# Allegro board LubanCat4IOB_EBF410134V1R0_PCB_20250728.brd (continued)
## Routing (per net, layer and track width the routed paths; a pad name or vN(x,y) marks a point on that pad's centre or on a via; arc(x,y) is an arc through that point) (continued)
PCIE20_0_RXP: length 112
  TOP w0.15: J5.4 49.68,24.47 49.72,24.44 49.72,24.02 49.26,23.57 48.05,23.57 47.88,23.73 v1(47.48,23.73) ; v1(48.23,55.75) 48.44,55.96 48.44,57.28 54.19,63.04 66.91,63.04 72.09,68.22 90.62,68.22 91.37,68.97 91.37,72.91 92.59,74.13 97.62,74.13 99.58,76.09 103.89,76.09 104.7,76.91 106.65,76.91 107.04,77.3 107.04,77.71 106.8,77.94 J25.25
  BOTTOM w0.15: v1(48.23,55.75) 48.44,55.55 48.44,54.31 49.53,53.22 49.53,27.9 arc(49.47,27.75) 49.32,27.69 arc(49.17,27.63) 49.1,27.48 49.1,27.3 arc(49.17,27.15) 49.32,27.09 arc(49.47,27.03) 49.53,26.88 49.53,25.37 arc(49.47,25.23) 49.33,25.17 arc(49.18,25.11) 49.12,24.97 49.12,24.77 arc(49.18,24.63) 49.33,24.57 arc(49.47,24.51) 49.53,24.37 49.53,24.08 49.01,23.57 48.05,23.57 47.88,23.73 v1(47.48,23.73)
PCIE20_0_TXN: length 94.2
  TOP w0.15: v1(48.57,58.78) 48.42,58.93 48.42,59.14 53.36,64.08 66.38,64.08 71.51,69.21 89.21,69.21 89.7,69.71 89.7,70.53 C156.1 ; v1(52.65,23.79) 52.24,23.79 52.08,23.62 51.25,23.62 50.84,24.02 50.84,24.44 50.88,24.47 J5.10
  BOTTOM w0.15: v1(52.65,23.79) 52.24,23.79 52.08,23.62 51.7,23.62 51.44,23.89 51.44,24.72 51.79,25.07 53.22,25.07 53.92,25.78 53.92,29.04 52.76,30.21 52.76,31.95 arc(52.82,32.11) 52.98,32.18 arc(53.15,32.24) 53.21,32.41 53.21,32.55 arc(53.15,32.71) 52.98,32.78 arc(52.82,32.84) 52.76,33.01 52.76,33.15 arc(52.82,33.31) 52.98,33.38 arc(53.15,33.44) 53.21,33.6 53.21,33.75 arc(53.15,33.91) 52.98,33.98 arc(52.82,34.04) 52.76,34.2 52.76,57.23 52.02,57.96 48.72,57.96 48.4,58.27 48.4,58.62 v1(48.57,58.78)
PCIE20_0_TXP: length 94.3
  TOP w0.15: v1(52.65,23.13) 52.24,23.13 52.08,23.29 51.11,23.29 50.52,23.89 50.52,24.44 50.48,24.47 J5.8 ; v1(47.91,58.78) 48.09,58.96 48.09,58.98 48.1,58.99 48.1,59.28 53.23,64.41 66.24,64.41 71.37,69.54 89.07,69.54 89.37,69.84 89.37,70.53 C157.1
  BOTTOM w0.15: v1(52.65,23.13) 52.24,23.13 52.08,23.29 51.56,23.29 51.11,23.75 51.11,24.86 51.65,25.4 53.08,25.4 53.6,25.92 53.6,28.9 52.43,30.07 52.43,57.09 51.88,57.63 48.58,57.63 48.08,58.14 48.08,58.62 v1(47.91,58.78)
PCIE20X1_2_CLKREQN_M0: length 66.3
  TOP w0.152: v1(61.65,81.41) 61.15,80.91 61.15,79.45 59.68,77.98 J6.54
  ART03 w0.14: v1(61.65,81.41) 61.65,82.35 62.23,82.93 69.24,82.93 70.54,81.63 76.94,81.63 77.24,81.94 80.31,81.94 80.77,81.48 88.72,81.48 89.28,82.04 96.77,82.04 97.28,81.53 105.85,81.53 106.86,80.52 v1(116.71,80.52)
  BOTTOM w0.152: R179.1 116.71,79.38 v1(116.71,80.52)
PCIE20X1_2_PERSTN_M0: length 60.1
  TOP w0.152: J6.74 63.68,76.73 66.15,79.2 v1(66.15,80.39)
  TOP w0.203: v1(97.28,65.91) 98.17,65.02 99.31,65.02 100.84,66.55 101.85,66.55 103.89,68.58 R181.2
  ART03 w0.14: v1(66.15,80.39) 67.98,78.56 79.48,78.56 79.96,79.04 89.88,79.04 90.56,78.36 95.58,78.36 v1(95.7,78.48)
  BOTTOM w0.203: v1(97.28,65.91) 97.41,66.04 97.41,67.23 98.12,67.94 98.12,75.65 95.7,78.07 v1(95.7,78.48)
PCIE20X1_2_WAKEN_M0: length 68.5
  TOP w0.152: v1(61.65,80.39) 61.65,79.35 60.08,77.77 J6.56
  ART03 w0.14: v1(118.88,80.52) 118.36,80.52 117.3,79.46 97.81,79.46 96.22,81.05 90.32,81.05 89.26,79.98 77.27,79.98 76.73,80.52 69.39,80.52 68.5,81.41 64.26,81.41 63.98,81.13 63.98,79.95 63.7,79.67 61.93,79.67 61.65,79.95 v1(61.65,80.39)
  BOTTOM w0.152: v1(118.88,80.52) R178.1
PE_TXN: length 21
  TOP w0.15: J25.31 104.4,77.99 104.2,77.79 104.2,77.41 103.69,76.89 98.69,76.89 98.05,76.25 90.1,76.25 89.7,75.85 89.7,72.67 90.04,72.33 C156.2
PE_TXP: length 21.1
  TOP w0.15: J25.33 103.6,78.01 103.88,77.73 103.88,77.54 103.55,77.21 98.55,77.21 97.92,76.58 89.96,76.58 89.37,75.99 89.37,72.67 89.03,72.33 C157.2
PHY1_CLKOUT125: length 4.6
  BOTTOM w0.132: R97.2 107.19,66.17 107.19,67.81 107.45,68.08 109.09,68.08 U14.35
PHY1_LED1: length 59
  BOTTOM w0.152: J15.14 107.64,99 106.55,97.92 106.55,84.73 106.02,84.2 98.93,84.2 98.3,83.56 98.3,79.75 100.97,77.09 100.97,63.12 101.68,62.41 103.8,62.41 R103.1 105.04,63.65 106.07,63.65 108.01,65.59 108.01,66.86 108.47,67.32 U14.33
PHY1_LED2: length 69.7
  BOTTOM w0.152: U14.34 107.86,67.73 107.64,67.5 107.64,65.7 106.83,64.9 105.15,64.9 R102.1 103.9,63.65 101.53,63.65 101.35,63.83 101.35,77.34 98.81,79.88 98.81,83.31 99.19,83.69 106.53,83.69 106.98,84.15 106.98,96.54 107.21,96.77 121.4,96.77 J15.11
PWM7_IR_M0: length 62.8
  TOP w0.152: v1(15.37,12.06) 15.77,11.66 18.16,11.66 18.67,12.17 18.67,16.59 18.97,16.89 62.23,16.89 63.5,18.16 63.5,22.99 62.88,23.61 J5.70
  BOTTOM w0.152: R45.1 C46.1 v1(15.37,12.06)
PWRON_EN: length 4.2
  TOP w0.152: v1(27.3,22.48) 27.66,22.48 28.11,22.93 J3.24
  BOTTOM w0.152: R238.2 v1(27.3,22.48)
PWRON_KEY: length 35.2
  TOP w0.152: v1(8.13,21.84) 8.66,21.31 28.42,21.31 28.91,21.8 J3.28
  TOP w0.381: SW1.3 v1(3.43,20.07) SW1.4
  BOTTOM w0.152: v1(3.43,20.07) 3.45,20.06 Z1.2 C39.1 5.21,21.33 5.71,21.84 v1(8.13,21.84)
RESET_KEY: length 33.5
  TOP w0.203: J3.26 28.51,22.57 27.79,21.84 9.14,21.84 v1(8.13,22.86)
  TOP w0.381: SW2.3 v1(3.49,24.46) SW2.4
  BOTTOM w0.254: v1(8.13,22.86) 6.47,24.52 C41.1 Z2.2 3.55,24.52 v1(3.49,24.46)
RS485_1_A: length 31
  TOP w0.305: R67.1 93.34,19.14 93.67,19.46 J11.1
  BOTTOM w0.305: J11.1 92.76,19.76 91.57,19.76 91.26,20.06 91.26,21.65 90.5,22.41 90.5,31.68 D20.2 90.5,35.34 90.5,40.83 R62.2 90.52,41.44 90.52,42.13 90.93,42.54 U10.6
RS485_1_B: length 32.7
  TOP w0.305: R66.1 R63.1 v1(94.83,19.3)
  BOTTOM w0.305: U10.7 89.66,42.54 90.06,42.15 90.06,41.63 89.65,41.23 R64.1 90.04,40.76 90.04,35.29 D18.2 90.04,31.73 90.04,22.22 90.81,21.46 90.81,19.88 91.38,19.3 v1(94.83,19.3)
RS485_2_A: length 30.9
  TOP w0.305: J13.1 85.92,19.46 85.72,19.27 R69.1
  BOTTOM w0.305: J13.1 85.01,19.76 84.2,19.76 83.71,20.25 83.71,29.1 82.58,30.23 82.58,31.63 D22.2 82.62,35.34 82.62,40.83 R70.2 82.63,41.46 82.63,41.99 83.06,42.42 U11.6
RS485_2_B: length 32.6
  TOP w0.305: v1(87.21,19.3) R71.1 R68.1
  BOTTOM w0.305: v1(87.21,19.3) 84.01,19.3 83.25,20.06 83.25,28.91 82.04,30.12 82.04,31.87 80.4,33.51 D21.2 82.17,35.29 82.17,40.76 R72.1 82.14,41.51 82.14,41.94 81.79,42.29 U11.7
RTC_32K_IN: length 132.8
  TOP w0.152: J5.50 58.88,23.45 54.36,18.92 32.13,18.92 31.37,18.16 18.41,18.16 17.91,17.65 17.91,13.33 v1(17.27,12.7)
  ART03 w0.14: v1(3.3,79.88) 3.3,71.82 3.12,71.64 3.12,69.36 2.67,68.9 2.67,59.74 3.07,59.33 3.07,42.77 5.08,40.77 5.08,19.12 9.21,14.98 17.27,14.98 17.78,14.48 17.78,13.21 v1(17.27,12.7)
  BOTTOM w0.152: R48.2 5.46,80.39 4.95,79.88 v1(3.3,79.88)
RTC_INT: length 135.4
  TOP w0.152: v1(17.27,13.71) 17.27,18.03 17.91,18.67 30.99,18.67 31.75,19.43 53.98,19.43 58.48,23.93 J5.48
  ART03 w0.152: v1(17.27,13.71) 9.14,13.71 4.45,18.41 4.45,40.38 2.06,42.77 2.06,69.62 2.49,70.05 2.49,71.07 2.06,71.5 2.06,79.04 2.54,79.53 v1(2.54,82.68)
  BOTTOM w0.152: U8.3 1.59,85.41 1.27,85.09 1.27,83.06 1.65,82.68 v1(2.54,82.68) 2.55,82.67 R46.2
RXD1_232: length 37.6
  BOTTOM w0.254: R51.1 36.45,29.59 35.31,30.73 D8.2 33.03,33.51 32.46,34.09 32.46,40.08 34.67,42.29 34.67,44.96 36.45,46.73 41.53,46.73 41.79,46.99 U9.13
RXD2_232: length 27
  BOTTOM w0.254: U9.8 36.71,39.87 37.21,39.37 37.21,36.7 38,35.91 40.65,35.91 D7.2 42.92,33.38 42.92,23.25 44.07,22.1 R49.1
SARADC_BOOT: length 78.4
  TOP w0.152: J4.52 33.71,77.3 32.38,78.63 32.38,79.01 29.67,81.73 18.62,81.73 v1(18.05,82.29)
  BOTTOM w0.152: R239.2 6.23,40.78 7.37,40.78 7.58,40.57 11.54,40.57 12.52,41.54 12.52,58.23 15.34,61.05 15.34,68.57 14.96,68.95 11.48,68.95 10.69,69.74 10.69,71.31 10.13,71.87 10.13,74.56 12.88,77.31 12.88,79.62 13.26,80 14.4,80 15.16,80.76 15.16,81.68 15.78,82.29 v1(18.05,82.29)
SARADC_IN1/REC: length 80.9
  TOP w0.203: J4.50 33.31,77.15 29.45,81.01 17.55,81.01 v1(17.08,81.48)
  BOTTOM w0.203: R28.2 8.5,27.82 10.41,29.73 10.41,35.57 15.11,40.27 15.11,57.02 17.91,59.82 17.91,68.85 17.27,69.48 17.27,71.01 17.65,71.39 17.65,77.87 18.01,78.22 18.01,80.55 v1(17.08,81.48)
SARADC_IN4: length 70.1
  TOP w0.203: J4.46 32.51,76.22 28.26,80.48 v1(17.08,80.48)
  BOTTOM w0.203: R31.2 8.96,35.31 14.35,40.71 14.35,57.42 16.76,59.83 16.76,71.39 17.05,71.68 17.05,78.49 17.6,79.04 17.6,79.96 v1(17.08,80.48)
SARADC_IN5: length 65.7
  TOP w0.203: v1(17.08,79.48) 17.48,79.87 28.13,79.87 32.11,75.89 J4.44
  BOTTOM w0.203: v1(17.08,79.48) 16.26,78.65 16.26,70.75 15.94,70.44 15.94,60.4 13.34,57.8 13.34,40.99 8.94,36.59 R33.2
SBU_1: length 26.7
  TOP w0.135: v1(27.07,95) 27.12,95.05 J30.A8
  BOTTOM w0.135: v1(27.07,95) 25.87,96.19 25.87,99.66 26.25,100.04 29.75,100.04 30.26,99.53 30.26,99.37 30.76,98.87 35.11,98.87 35.54,98.44 35.54,97.71 35.45,97.62 U37.1 U37.10 35.45,95.67 35.54,95.58 35.54,95.39 35.28,95.12 33.69,95.12 32.36,93.79 32.36,93.45 R229.1
  BOTTOM w0.152: R226.1 C201.1 32,92.07 R229.1
SBU_2: length 19.1
  TOP w0.135: v1(30.73,99.57) 30.23,99.57 29.72,99.06 29.27,99.06 28.96,98.74 28.96,98.04 28.87,97.96 J30.B8
  BOTTOM w0.135: v1(30.73,99.57) 30.73,99.39 30.94,99.19 35.24,99.19 35.86,98.57 35.86,97.71 35.95,97.62 U37.2 U37.9 35.95,95.67 35.86,95.58 35.86,95.26 35.41,94.81 33.82,94.81 32.67,93.66 32.67,93.45 R228.1
  BOTTOM w0.152: R228.1 33.03,92.07 C202.1 R227.1
SDMMC_CLK: length 87.7
  TOP w0.132: J6.77 64.48,70.08 64.95,69.6 v1(65.63,69.6) ; v1(107.14,27.98) 107.36,27.98 R57.1
  BOTTOM w0.132: v1(65.63,69.6) 66.14,69.1 66.14,67.86 66.4,67.6 67.87,67.6 68.16,67.31 68.16,56.5 70.78,53.88 95.57,53.88 101.85,47.59 101.85,41.01 101.99,40.88 102.51,40.88 102.64,40.75 102.64,40.48 102.51,40.35 101.99,40.35 101.85,40.22 101.85,39.95 101.99,39.82 102.51,39.82 102.64,39.69 102.64,39.43 102.51,39.29 101.99,39.29 101.85,39.16 101.85,38.9 101.99,38.76 102.51,38.76 102.64,38.63 102.64,38.37 102.51,38.24 101.99,38.24 101.85,38.1 101.85,37.84 101.99,37.71 102.51,37.71 102.64,37.58 102.64,37.31 102.51,37.18 101.99,37.18 101.85,37.05 101.85,36.78 101.99,36.65 102.51,36.65 102.64,36.52 102.64,36.26 102.51,36.12 101.99,36.12 101.85,35.99 101.85,35.73 101.99,35.59 102.51,35.59 102.64,35.46 102.64,35.2 102.51,35.07 101.99,35.07 101.85,34.93 101.85,29.85 102.63,29.07 106.58,29.07 107.14,28.51 v1(107.14,27.98)
SDMMC_CMD: length 87.8
  TOP w0.132: J6.79 64.88,70.38 65.14,70.12 66.12,70.12 v1(66.63,69.6) ; R55.1 v1(111.25,29.08)
  BOTTOM w0.132: v1(66.63,69.6) 67.21,69.03 69.64,69.03 69.9,68.76 69.9,67.85 69.77,67.72 69.29,67.72 69.15,67.59 69.15,67.32 69.29,67.19 69.77,67.19 69.9,67.06 69.9,66.8 69.77,66.66 69.29,66.66 69.15,66.53 69.15,66.27 69.29,66.13 69.77,66.13 69.9,66 69.9,65.74 69.77,65.61 69.29,65.61 69.15,65.47 69.15,65.21 69.29,65.08 69.77,65.08 69.9,64.95 69.9,64.68 69.77,64.55 69.29,64.55 69.15,64.42 69.15,56.86 71.26,54.75 95.93,54.75 102.87,47.81 102.87,42.53 103.66,41.75 103.66,34.25 102.87,33.47 102.87,31.06 103.89,30.04 107.34,30.04 107.82,29.56 110.78,29.56 v1(111.25,29.08)
SDMMC_D0: length 88.8
  TOP w0.132: R58.1 106.09,27.98 v1(105.87,27.98) ; v1(65.63,67) 63.25,67 62.88,67.37 J6.69
  BOTTOM w0.132: v1(105.87,27.98) 105.31,27.42 100.81,27.42 100.33,27.9 100.33,47.24 95.01,52.57 67.39,52.57 65.94,54.02 65.94,56.52 66.07,56.66 66.49,56.66 66.62,56.79 66.62,57.05 66.49,57.18 66.07,57.18 65.94,57.32 65.94,57.58 66.07,57.71 66.49,57.71 66.62,57.84 66.62,58.11 66.49,58.24 66.07,58.24 65.94,58.37 65.94,58.64 66.07,58.77 66.49,58.77 66.62,58.9 66.62,59.17 66.49,59.3 66.07,59.3 65.94,59.43 65.94,59.69 66.07,59.83 66.49,59.83 66.62,59.96 66.62,60.22 66.49,60.35 66.07,60.35 65.94,60.49 65.94,60.75 66.07,60.88 66.49,60.88 66.62,61.01 66.62,61.28 66.49,61.41 66.07,61.41 65.94,61.54 65.94,65.78 65.63,66.09 v1(65.63,67)
SDMMC_D1: length 88.1
  TOP w0.132: J6.71 63.28,68 63.68,67.6 65.08,67.6 v1(65.63,68.16) ; v1(104.6,27.98) 104.82,27.98 R59.1
  BOTTOM w0.132: v1(104.6,27.98) 102.29,27.98 100.84,29.43 100.84,47.37 95.2,53 68.79,53 68.66,53.14 68.66,54.26 68.52,54.4 68.26,54.4 68.13,54.26 68.13,53.14 68,53 67.74,53 67.46,53.28 67.46,54.05 67.2,54.31 66.63,54.31 66.5,54.44 66.5,54.71 66.65,54.86 67.58,54.86 67.72,55 67.72,55.26 67.58,55.39 66.63,55.39 66.5,55.52 66.5,55.76 66.63,55.9 67.08,55.9 67.21,56.03 67.21,64 67.08,64.13 66.51,64.13 66.38,64.26 66.38,64.53 66.51,64.66 67.08,64.66 67.21,64.79 67.21,65.47 67.06,65.62 66.71,65.62 66.45,65.89 66.45,66.41 66.13,66.73 66.13,67.21 65.63,67.71 v1(65.63,68.16)
SDMMC_D2: length 88.7
  TOP w0.132: R53.1 113.79,28.7 v1(113.41,29.08) ; J6.73 63.68,69.08 64.06,68.7 66.09,68.7 v1(66.63,68.16)
  BOTTOM w0.132: v1(66.63,68.16) 66.67,68.12 68.43,68.12 68.67,67.88 68.67,56.61 70.97,54.31 95.75,54.31 102.36,47.7 102.36,42.05 103.12,41.29 103.12,34.71 102.36,33.95 102.36,30.95 103.73,29.58 107.06,29.58 108.25,28.39 111.67,28.39 111.94,28.65 111.94,29.49 112.2,29.76 113.15,29.76 113.41,29.49 v1(113.41,29.08)
SDMMC_D3: length 88.6
  TOP w0.132: v1(66.63,67) 67.36,67.73 67.36,68.72 66.98,69.1 64.47,69.1 64.08,69.49 J6.75 ; R54.1 v1(112.52,29.08)
  BOTTOM w0.132: v1(112.52,29.08) 112.52,28.13 111.66,27.27 106.98,27.27 106.6,27.65 106.6,28.28 106.25,28.64 102.45,28.64 101.35,29.74 101.35,47.48 95.39,53.44 70.51,53.44 67.65,56.3 67.65,65.99 v1(66.63,67)
SDMMC_DET: length 77.7
  TOP w0.152: v1(68.63,69.6) 67.74,70.5 65.51,70.5 65.28,70.73 J6.81 ; v1(103.38,31.37) 103.38,29.46 103.89,28.95 R60.1 R61.2
  BOTTOM w0.152: v1(68.63,69.6) 70.12,69.6 70.51,69.21 70.51,56.13 71.45,55.2 96.11,55.2 103.38,47.93 103.38,42.95 104.17,42.16 104.17,33.82 103.38,33.03 v1(103.38,31.37)
SIM_CLK0: length 36.4
  TOP w0.152: J25.12 115.2,69.48 114.94,69.21 114.94,60.2 113.73,59 113.73,57.47 116.97,54.23 116.97,37.46 116.75,37.25 v1(116.71,37.25)
  BOTTOM w0.132: v1(116.71,37.25) R171.1
SIM_DATA0: length 40.5
  TOP w0.152: v1(113.49,36.45) 117.09,36.45 117.47,36.83 117.47,54.48 114.87,57.09 114.87,59.37 115.44,59.94 115.44,68.96 116,69.52 J25.10
  BOTTOM w0.132: R173.1 113.61,36.57 v1(113.49,36.45)
SIM_RST0: length 42.1
  TOP w0.152: v1(113.16,34.8) 112.9,35.05 112.9,36.57 113.28,36.96 115.32,36.96 116.46,38.1 116.46,54.1 112.59,57.97 112.59,58.99 114.55,60.96 114.55,69.11 114.4,69.26 J25.14
  BOTTOM w0.132: R170.1 v1(113.16,34.8)
SIM_VDD: length 61.2
  TOP w0.305: J25.8 116.8,69.56 116.01,68.77 116.01,56.83 118.11,54.74 118.11,37.34 v1(117.98,37.21)
  BOTTOM w0.305: J31.1 110.75,23.29 111.05,23.6 113,23.6 114.43,25.02 114.43,29.59 114.77,29.93 U32.1 113.28,30.87 112.39,31.75 112.39,36.57 113.28,37.46 115.14,37.46 115.44,37.16 ; 115.44,37.16 R169.1 ; 115.44,37.16 116.13,37.84 117.35,37.84 v1(117.98,37.21)
SPK_CTRL: length 45.5
  TOP w0.152: J4.24 28.11,77.68 27.3,78.48 16,78.48 15.6,78.89 15.6,82.4 16,82.8 19.56,82.8 19.94,83.18 v1(19.94,84.48)
  ART03 w0.14: v1(35.69,85.14) 34.56,85.14 34,85.7 27.58,85.7 26.92,86.36 26.31,86.36 25.3,85.34 24.64,85.34 23.77,84.48 v1(19.94,84.48)
  BOTTOM w0.152: U34.1 35.06,83.56 R214.1 35.43,84.89 v1(35.69,85.14)
SS_TXN: length 16.1
  BOTTOM w0.135: C97.1 85.19,83.02 85.19,83.47 85.05,83.61 85.05,84.02 84.95,84.12 U17.7 U17.4 84.95,86.06 85.05,86.16 85.05,87.02 83.82,88.25 83.82,89.34 84.65,90.17 84.65,90.49 85.47,91.31 86.4,91.31 86.65,91.06 87.26,91.06 87.47,91.26 88.37,91.26 88.7,90.93 89.15,90.93 89.76,91.54 89.76,91.75 89.62,91.88 J16.8
SS_TXP: length 16.1
  BOTTOM w0.135: C98.1 85.5,83.02 85.5,83.6 85.36,83.74 85.36,84.02 85.45,84.12 U17.6 U17.5 85.45,86.06 85.36,86.16 85.36,87.15 84.13,88.38 84.13,89.21 84.96,90.04 84.96,90.36 85.6,91 86.27,91 86.52,90.75 87.39,90.75 87.6,90.95 88.24,90.95 88.57,90.62 89.28,90.62 90.07,91.41 90.07,91.75 90.21,91.88 J16.9
SSRX_1N: length 14.4
  TOP w0.135: R223.1 31.35,92.72 U35.5 U35.6 31.35,94.63 31.59,94.87 32.88,94.87 33.91,95.9 33.91,98.47 33.39,98.99 30.33,98.99 29.96,98.63 29.96,98.19 29.87,98.09 J30.B10
SSRX_1P: length 14
  TOP w0.135: J30.B11 30.37,98.03 30.28,98.12 30.28,98.5 30.46,98.68 32.17,98.68 arc(32.26,98.64) 32.3,98.55 arc(32.34,98.46) 32.43,98.42 32.71,98.42 arc(32.8,98.46) 32.84,98.55 arc(32.88,98.64) 32.97,98.68 33.26,98.68 33.59,98.34 33.59,98.08 arc(33.55,97.97) 33.44,97.92 arc(33.33,97.88) 33.28,97.77 33.28,97.54 arc(33.33,97.43) 33.44,97.39 arc(33.55,97.34) 33.59,97.23 33.59,96.03 32.75,95.18 31.46,95.18 30.86,94.58 30.86,94.17 U35.7 U35.4 30.85,92.78 31.4,92.22 31.4,91.97 R222.1
SSRX_2N: length 4.7
  TOP w0.135: R225.1 26.75,92.24 26.75,92.76 26.65,92.85 U36.5 U36.6 26.47,94.34 26.47,94.59 26.47,94.6 26.47,95.13 26.47,95.13 26.47,95.2 26.13,95.54 J30.A10
SSRX_2P: length 4.7
  TOP w0.135: J30.A11 25.63,95.6 26.15,95.07 26.15,95 U36.7 U36.4 26.15,92.91 26.43,92.63 26.43,92.08 R224.1
SSTX_1N: length 4.6
  TOP w0.135: C198.1 29.13,92.24 29.13,92.5 29.35,92.72 U35.1 U35.10 29.35,94.5 29.54,94.69 29.54,95.08 29.63,95.17 J30.A3
SSTX_1P: length 4.6
  TOP w0.135: J30.A2 30.13,95.47 29.94,95.29 29.94,95.04 29.85,94.95 29.85,94.16 U35.9 U35.2 29.85,92.77 29.45,92.37 29.45,92.08 C197.1
SSTX_2N: length 16.3
  TOP w0.135: C200.1 24.65,92.59 U36.1 U36.10 24.65,94.47 24.48,94.64 arc(24.44,94.67) 24.39,94.68 22.75,94.68 arc(22.24,94.78) 21.81,95.07 arc(21.63,95.33) 21.57,95.64 21.57,98.34 arc(21.65,98.72) 21.86,99.04 21.86,99.04 arc(22.2,99.26) 22.59,99.34 25.5,99.34 arc(25.78,99.29) 26.03,99.14 arc(26.21,98.9) 26.28,98.61 26.28,98.19 26.37,98.1 J30.B3
SSTX_2P: length 16.2
  TOP w0.135: C199.1 24.7,92 24.7,92.19 25.15,92.65 U36.2 U36.9 25.15,94.5 arc(25.12,94.68) 25.01,94.84 arc(24.84,94.95) 24.64,94.99 22.75,94.99 arc(22.36,95.07) 22.03,95.29 arc(21.92,95.45) 21.88,95.64 21.88,96.13 arc(21.93,96.25) 22.05,96.3 arc(22.17,96.34) 22.21,96.46 22.21,96.67 arc(22.17,96.79) 22.05,96.83 arc(21.93,96.88) 21.88,97 21.88,97.21 arc(21.93,97.32) 22.05,97.37 arc(22.17,97.42) 22.21,97.54 22.21,97.75 arc(22.17,97.86) 22.05,97.91 arc(21.93,97.96) 21.88,98.08 21.88,98.34 arc(21.94,98.6) 22.08,98.81 arc(22.31,98.97) 22.59,99.02 25.5,99.02 arc(25.67,98.99) 25.83,98.9 arc(25.93,98.77) 25.96,98.61 25.96,98.19 25.87,98.1 J30.B2
SYS_LED: length 57.4
  TOP w0.152: J5.65 v1(62.08,26.77)
  ART03 w0.14: v1(62.08,26.77) 62.08,25.3 61.85,25.07 33.32,25.07 32.99,24.74 32.99,21.62 32.2,20.83 v1(12.06,20.83)
  BOTTOM w0.152: v1(12.06,20.83) 11.44,20.2 R38.1
TX_CEC_PORT: length 10.7
  TOP w0.156: J18.13 68.5,94.74 68.68,94.92 68.68,95.6 68.53,95.76 65.57,95.76 v1(64.93,95.12)
  BOTTOM w0.152: Q9.3 63.75,95.49 D33.2 64.38,95.12 v1(64.93,95.12)
TX_D0N_PORT: length 9.2
  TOP w0.107: J18.9 66.5,91.75 66.39,91.65 66.3,91.65 66.19,91.54 66.19,91.32 66.73,90.79 67.63,90.79 68.21,90.21 U23.4 U23.7 68.21,88.63 67.95,88.38 67.95,87.85 v1(68.05,87.76) 67.85,87.56 67.85,87.33 R136.1
  BOTTOM w0.107: R136.1 67.84,87.34 67.84,87.55 v1(68.05,87.76)
TX_D0P_PORT: length 9.2
  TOP w0.107: R134.1 67.57,87.37 67.57,87.57 v1(67.39,87.76) 67.67,88.04 67.67,88.5 67.71,88.53 U23.6 U23.5 67.71,90.31 67.51,90.5 66.61,90.5 65.91,91.2 65.91,91.54 65.8,91.65 65.61,91.65 65.5,91.75 J18.7
  BOTTOM w0.107: R134.1 67.56,87.36 67.56,87.59 v1(67.39,87.76)
TX_D1N_PORT: length 8.1
  TOP w0.107: J18.6 65,91.75 64.89,91.65 64.8,91.65 64.69,91.54 64.69,91.39 65.07,91.01 65.07,90.77 65.26,90.59 U22.1 U22.10 65.26,88.56 65.46,88.37 65.46,88.09 65.71,87.83 65.71,87.81 v1(65.76,87.76) 65.56,87.55 65.56,87.34 R138.1
  BOTTOM w0.107: v1(65.76,87.76) 65.56,87.56 65.56,87.34 R138.1
TX_D1P_PORT: length 8.1
  TOP w0.107: R137.1 65.27,87.36 65.27,87.58 v1(65.1,87.76) 65.17,87.83 65.17,88.25 64.76,88.66 U22.9 U22.2 64.76,90.63 64.79,90.66 64.79,90.89 64.41,91.27 64.41,91.49 64.25,91.65 64.11,91.65 64,91.75 J18.4
  BOTTOM w0.107: R137.1 65.28,87.36 65.28,87.58 v1(65.1,87.76)
TX_D2N_PORT: length 8
  TOP w0.107: J18.3 63.5,91.77 63.24,91.51 63.24,90.94 63.58,90.61 63.58,90.47 63.76,90.29 U22.4 U22.7 63.76,88.7 63.35,88.29 63.35,87.87 63.44,87.78 v1(63.44,87.76) 63.25,87.58 63.25,87.36 R141.1
  BOTTOM w0.107: R141.1 63.26,87.35 63.26,87.59 v1(63.44,87.76)
TX_D2P_PORT: length 8
  TOP w0.107: R140.1 62.97,87.34 62.97,87.56 v1(62.78,87.76) 63.06,88.04 63.06,88.41 63.26,88.61 U22.6 U22.5 63.26,90.52 62.96,90.82 62.96,91.34 62.5,91.8 J18.1
  BOTTOM w0.107: v1(62.78,87.76) 62.98,87.55 62.98,87.37 62.61,87 R140.1
TX_D3N_PORT: length 9.3
  TOP w0.107: R144.1 70.25,87.34 70.25,87.58 v1(70.43,87.76) 70.06,88.13 70.06,88.29 69.71,88.64 U23.10 U23.1 69.71,90.79 69.33,91.18 69.01,91.18 68.9,91.29 68.58,91.29 68.47,91.18 68.23,91.18 67.86,91.54 67.86,91.69 68,91.82 J18.12
  BOTTOM w0.107: R144.1 70.25,87.34 70.25,87.58 v1(70.43,87.76)
TX_D3P_PORT: length 9.4
  TOP w0.107: R143.1 69.97,87.36 69.97,87.56 v1(69.77,87.76) 69.77,88.17 69.21,88.74 U23.9 U23.2 69.21,90.78 69.1,90.89 68.11,90.89 67.8,91.2 67.6,91.2 67,91.8 J18.10
  BOTTOM w0.107: R143.1 69.97,87.36 69.97,87.56 v1(69.77,87.76)
TX_ON: length 16.4
  TOP w0.152: Q13.1 62.51,83.31 63.98,83.31 Q14.1 65.68,83.31 67.16,83.31 Q15.1 68.86,83.31 70.33,83.31 Q12.1 71.19,82.46 72.04,83.31 73.15,83.31 73.78,83.94 R146.1 R145.2
TX_SCL_PORT: length 20.3
  TOP w0.156: v1(61.47,95.12) 61.47,96.9 62.21,97.64 67.33,97.64 69.5,95.47 J18.15
  BOTTOM w0.152: R128.2 65.42,91.81 65.29,91.68 65.16,91.68 64.48,92.37 Q7.3 63.75,93.1 D31.2 61.72,93.6 61.47,93.85 v1(61.47,95.12)
TX_SDA_PORT: length 12.9
  TOP w0.156: v1(72.14,93.64) 72.14,95.44 71.82,95.76 70.25,95.76 70,95.5 J18.16
  BOTTOM w0.152: v1(72.14,93.64) 72.05,93.72 70.73,93.72 D30.2 70.6,92.95 70.1,92.45 Q8.3 67.48,92.37 R131.2
TXD1_232: length 40
  BOTTOM w0.254: R52.1 38.1,30.38 39.12,31.4 D10.2 37.07,35.56 33.66,35.56 33.27,35.94 33.27,39.37 35.59,41.68 35.59,44.67 36.51,45.59 42.16,45.59 43.05,46.48 U9.14
TXD2_232: length 29.8
  BOTTOM w0.254: U9.7 37.97,40.51 38.48,40 44.32,40 45.09,39.24 45.09,35.29 D9.2 46.86,31.62 45.85,30.61 R50.1
TYPE_C_PWR_EN: length 95.2
  TOP w0.152: J6.66 62.08,77.17 64.15,79.24 64.15,80.66 64.44,80.95 75.87,80.95 76.83,81.91 v1(76.83,92.33)
  ART03 w0.14: v1(76.83,92.33) 76.2,91.69 71.63,91.69 71.12,92.2 61.72,92.2 60.88,91.36 56.14,91.36 54.77,89.99 51.55,89.99 49.85,91.69 44.93,91.69 43.54,90.3 38.53,90.3 36.37,88.14 35.05,88.14 34.52,88.67 28.47,88.67 27.99,88.19 22.26,88.19 21.59,87.52 v1(21.59,86.49)
  BOTTOM w0.152: R236.1 19.44,86.79 19.74,86.49 v1(21.59,86.49)
TYPEC0_OTG_DM: length 27.3
  TOP w0.135: J4.98 42.91,75.65 42.87,75.69 42.87,86.67 42.6,86.94 42.6,87.58 v1(42.78,87.76) ; R221.2 33.83,90.51 33.83,89.9 34.2,89.53 36.98,89.53 37.43,89.99 37.43,91.02 v1(37.59,91.18)
  BOTTOM w0.135: v1(37.59,91.18) 37.38,90.97 37.38,90.59 37.68,90.3 41.71,90.3 42.58,89.43 42.58,87.96 v1(42.78,87.76)
TYPEC0_OTG_DP: length 26.3
  TOP w0.135: v1(42.12,87.76) 42.29,87.58 42.29,86.81 42.56,86.54 42.56,75.69 42.51,75.65 J4.96 ; v1(36.93,91.18) 37.12,91 37.12,90.12 36.85,89.85 34.33,89.85 34.14,90.03 34.14,90.41 R220.2
  BOTTOM w0.135: v1(36.93,91.18) 37.07,91.05 37.07,90.46 37.55,89.98 41.59,89.98 42.27,89.3 42.27,87.91 42.12,87.77 v1(42.12,87.76)
TYPEC0_OTG_VBUSDET: length 9.8
  TOP w0.152: v1(43.94,77.21) 44.48,76.68 44.48,74.34 44.12,73.99 41.98,73.99 41.71,74.25 J4.92
  BOTTOM w0.152: v1(43.94,77.21) 44.33,77.6 R233.2
TYPEC0_SBU1/DP0_AUXP: length 20.7
  TOP w0.135: J4.84 40.11,75.65 40.16,75.69 40.16,79.86 arc(40.11,80.08) 39.99,80.27 39.95,80.31 arc(39.65,80.75) 39.55,81.28 39.55,82.78 arc(39.46,83.19) 39.23,83.54 37.87,84.9 arc(37.7,85.15) 37.65,85.44 arc(37.65,85.44) 37.65,85.45 arc(37.6,85.67) 37.48,85.85 v1(37.47,85.86)
  BOTTOM w0.135: v1(37.47,85.86) 37.56,85.94 37.56,87.46 arc(37.47,87.88) 37.24,88.24 35.44,90.03 arc(35.22,90.18) 34.96,90.23 33.02,90.23 arc(32.85,90.27) 32.7,90.37 C201.2
TYPEC0_SBU1_DC: length 81.1
  TOP w0.152: v1(69.02,73.57) 67.85,73.57 67.54,73.26 67.54,72.37 67.68,72.23 J6.93 ; v1(77.47,93.72) 77.72,93.47 77.72,81.53 v1(77.85,81.41)
  ART03 w0.14: v1(35.96,88.66) 36.31,88.66 38.4,90.75 43.26,90.75 44.7,92.2 49.99,92.2 51.77,90.42 54.58,90.42 56.05,91.89 60.58,91.89 61.47,92.78 71.31,92.78 71.98,92.1 75.46,92.1 77.09,93.72 v1(77.47,93.72)
  BOTTOM w0.152: v1(69.02,73.57) 70.43,74.97 70.43,76.65 72.9,79.12 74.19,79.12 74.8,79.73 74.8,80.77 75.44,81.41 v1(77.85,81.41) ; v1(35.96,88.66) 35.94,88.68 35.94,88.77 34.93,89.79 32.27,89.79 R226.2
TYPEC0_SBU2/DP0_AUXN: length 20.6
  TOP w0.135: J4.86 40.51,75.65 40.47,75.69 40.47,79.86 arc(40.4,80.2) 40.21,80.49 40.17,80.53 arc(39.94,80.87) 39.86,81.28 39.86,82.78 arc(39.75,83.31) 39.45,83.77 38.09,85.12 arc(37.99,85.27) 37.96,85.44 arc(37.96,85.44) 37.96,85.44 37.96,85.45 arc(38.01,85.67) v1(38.13,85.86)
  BOTTOM w0.135: C202.2 33.01,91.07 32.81,90.87 32.81,90.7 32.93,90.59 arc(32.97,90.56) 33.02,90.55 34.96,90.55 arc(35.34,90.47) 35.66,90.25 37.46,88.46 arc(37.76,88) 37.87,87.46 37.87,86.14 38.13,85.88 v1(38.13,85.86)
TYPEC0_SBU2_DC: length 80
  TOP w0.152: v1(68.02,72.57) 68.08,72.51 J6.95 ; v1(78.87,81.41) 78.16,82.11 78.16,94.17 v1(77.47,94.87)
  ART03 w0.14: v1(38.72,92.05) 39.23,92.56 40.87,92.56 41.48,93.17 44.32,93.17 44.81,92.68 50.19,92.68 52.07,90.8 54.15,90.8 55.7,92.35 60.27,92.35 61.24,93.32 71.45,93.32 72.24,92.53 75.13,92.53 v1(77.47,94.87)
  BOTTOM w0.152: v1(68.02,72.57) 68.51,73.05 69.27,73.05 71.43,75.21 71.43,76.94 73.2,78.71 74.4,78.71 75.23,79.55 75.23,80.57 75.59,80.92 78.38,80.92 v1(78.87,81.41) ; v1(38.72,92.05) 37.97,92.8 35.88,92.8 35.56,92.48 35.56,91.37 35.26,91.07 R227.2
TYPEC0_SSRX1N/DP0_TX0N: length 20.3
  TOP w0.135: J4.80 39.31,75.65 39.27,75.69 39.27,79.27 arc(39.12,80) 38.71,80.62 arc(38.45,81.01) 38.36,81.46 38.36,82.33 arc(38.23,82.97) 37.87,83.52 36.87,84.51 arc(36.58,84.95) 36.47,85.48 36.47,86.46 arc(36.36,87.06) 36.02,87.56 35.65,87.93 arc(35.07,88.31) 34.4,88.45 32.3,88.45 arc(32.02,88.57) 31.91,88.85 31.91,90.26 arc(31.94,90.45) 32.05,90.6 R223.2
TYPEC0_SSRX1P/DP0_TX0P: length 20.8
  TOP w0.135: J4.78 38.91,75.65 38.96,75.69 38.96,79.27 arc(38.83,79.88) 38.49,80.4 arc(38.16,80.89) 38.05,81.46 38.05,82.33 arc(37.94,82.85) 37.65,83.3 36.65,84.29 arc(36.29,84.83) 36.16,85.48 36.16,86.46 arc(36.07,86.94) 35.8,87.34 35.43,87.71 arc(34.96,88.03) 34.4,88.14 32.3,88.14 arc(31.8,88.34) 31.59,88.85 31.59,89.15 arc(31.54,89.29) 31.4,89.35 arc(31.27,89.4) 31.21,89.54 31.21,89.69 arc(31.27,89.83) 31.4,89.88 arc(31.54,89.94) 31.59,90.08 31.59,90.34 arc(31.57,90.45) 31.51,90.55 R222.2
TYPEC0_SSRX2N/DP0_TX2N: length 21.4
  TOP w0.135: J4.70 37.31,75.65 37.27,75.69 37.27,77.85 arc(37,79.2) 36.23,80.35 36.16,80.42 arc(35.95,80.74) 35.87,81.11 35.87,81.34 arc(35.7,82.22) 35.2,82.97 35.02,83.15 33.5,84.67 arc(32.41,85.4) 31.11,85.66 30.49,85.66 arc(29.54,85.84) 28.75,86.38 27.7,87.42 arc(27.05,88.39) 26.83,89.53 26.83,89.96 arc(26.92,90.42) R225.2
TYPEC0_SSRX2P/DP0_TX2P: length 21.4
  TOP w0.135: J4.68 36.91,75.65 36.96,75.69 36.96,77.85 arc(36.71,79.08) 36.01,80.12 35.94,80.19 arc(35.66,80.62) 35.56,81.11 35.56,81.34 arc(35.41,82.1) 34.98,82.75 34.8,82.93 33.28,84.44 arc(32.29,85.11) 31.11,85.34 30.49,85.34 arc(29.42,85.55) 28.52,86.16 27.48,87.2 arc(26.77,88.27) 26.51,89.53 26.51,89.96 arc(26.42,90.42) R224.2
TYPEC0_SSTX1N/DP0_TX1N: length 25.2
  TOP w0.135: v1(28.9,88.26) 28.94,88.34 arc(28.94,88.35) 28.94,88.36 28.94,90.24 arc(28.88,90.55) C198.2 ; J4.76 38.51,75.65 38.47,75.69 38.47,78.85 arc(38.38,79.3) 38.13,79.68 37.7,80.11 arc(37.45,80.48) 37.36,80.92 37.36,81.44 arc(37.18,82.33) 36.68,83.08 35.14,84.62 arc(34.98,84.86) 34.93,85.14 34.93,85.67 arc(34.96,85.84) v1(35.05,85.98)
  BOTTOM w0.135: v1(35.05,85.98) arc(35.02,86.02) 35.01,86.07 35.01,87.85 arc(34.65,88.74) 33.76,89.1 31.96,89.1 arc(31.91,89.11) 31.86,89.14 31.25,89.76 arc(31.1,89.86) 30.93,89.89 29.55,89.89 arc(29.13,89.72) 28.96,89.3 28.96,88.42 arc(28.95,88.34) v1(28.9,88.26)
TYPEC0_SSTX1P/DP0_TX1P: length 25.2
  TOP w0.135: C197.2 29.29,90.38 arc(29.26,90.34) 29.25,90.29 29.25,90.03 arc(29.3,89.91) 29.41,89.86 arc(29.53,89.82) 29.58,89.7 29.58,89.49 arc(29.53,89.37) 29.41,89.32 arc(29.3,89.28) 29.25,89.16 29.25,88.64 arc(29.26,88.58) 29.29,88.54 v1(29.56,88.27) ; J4.74 38.11,75.65 38.16,75.69 38.16,78.85 arc(38.09,79.18) 37.9,79.46 37.48,79.89 arc(37.16,80.36) 37.05,80.92 37.05,81.44 arc(36.89,82.21) 36.46,82.86 34.92,84.4 arc(34.69,84.74) 34.61,85.14 34.61,85.44 arc(34.56,85.73) v1(34.39,85.98)
  BOTTOM w0.135: v1(34.39,85.98) 34.56,86.15 arc(34.66,86.3) 34.7,86.49 34.7,87.85 arc(34.42,88.51) 33.76,88.79 31.96,88.79 arc(31.79,88.82) 31.64,88.92 31.03,89.54 arc(30.98,89.57) 30.93,89.58 30.66,89.58 30.51,89.42 29.97,89.42 29.81,89.58 29.55,89.58 arc(29.36,89.5) 29.27,89.3 29.27,88.61 arc(29.28,88.56) 29.31,88.52 v1(29.56,88.27)
TYPEC0_SSTX2N/DP0_TX3N: length 26.5
  TOP w0.135: C200.2 24.19,90.5 arc(24.22,90.46) 24.23,90.4 24.23,89.36 arc(24.18,89.13) v1(24.05,88.94) ; J4.66 36.51,75.65 36.47,75.69 36.47,77.35 arc(36.26,78.41) 35.66,79.31 35.42,79.55 arc(35.16,79.95) 35.06,80.42 arc(34.91,81.2) 34.46,81.87 32.18,84.15 arc(31.5,84.61) 30.7,84.77 29.6,84.77 arc(29.07,84.87) 28.62,85.17 28.48,85.31 arc(28.02,85.62) 27.48,85.72 27.03,85.72 arc(26.8,85.77) v1(26.61,85.9)
  BOTTOM w0.135: v1(24.05,88.94) 24.19,88.81 arc(24.22,88.76) 24.23,88.71 24.23,88.58 arc(24.37,88.22) 24.72,88.08 26.53,88.08 arc(26.95,87.99) 27.3,87.76 27.92,87.14 arc(28.12,86.84) 28.19,86.49 28.19,86.1 arc(28.08,85.84) 27.81,85.72 27.03,85.72 arc(26.8,85.77) v1(26.61,85.9)
TYPEC0_SSTX2P/DP0_TX3P: length 26.5
  TOP w0.135: C199.2 24.58,90.5 arc(24.55,90.46) 24.54,90.4 24.54,89.36 arc(24.59,89.13) v1(24.71,88.94) ; J4.64 36.11,75.65 36.16,75.69 36.16,77.35 arc(35.97,78.29) 35.44,79.09 35.2,79.33 arc(34.87,79.83) 34.75,80.42 arc(34.62,81.08) 34.24,81.65 31.96,83.93 arc(31.38,84.32) 30.7,84.45 29.6,84.45 arc(28.95,84.58) 28.4,84.95 28.26,85.09 arc(27.9,85.33) 27.48,85.41 27.03,85.41 arc(26.8,85.37) v1(26.61,85.24)
  BOTTOM w0.135: v1(24.71,88.94) 24.58,88.81 arc(24.55,88.76) 24.54,88.71 24.54,88.58 arc(24.59,88.45) 24.72,88.39 26.53,88.39 arc(27.07,88.28) 27.53,87.98 28.15,87.36 arc(28.41,86.96) 28.51,86.49 28.51,86.1 arc(28.3,85.61) 27.81,85.41 27.03,85.41 arc(26.8,85.37) v1(26.61,85.24)
TYPEC0_USB20_OTG_ID: length 12.9
  TOP w0.152: v1(44.83,77.21) 45.06,76.99 45.06,74.01 44.35,73.3 41.6,73.3 41.31,73.59 J4.90
  BOTTOM w0.152: v1(44.83,77.21) 43.31,75.69 R234.2
TYPEC_CC1: length 77
  TOP w0.152: J30.A5 28.62,95.23 v1(28.42,95.03)
  ART03 w0.135: v1(36.45,98.93) 33.91,98.93 33.53,98.55 33.53,95.25 ; v1(45.59,86.74) 45.65,86.74 45.79,86.61 45.79,86.25 42.76,83.22 19.66,83.22 19.34,82.9 19.34,82.59 v1(19.05,82.29)
  ART03 w0.152: 33.53,95.25 33.15,94.87 31.37,94.87 30.73,95.5 28.86,95.5 28.47,95.11 28.47,95.07 v1(28.42,95.03)
  BOTTOM w0.135: U39.11 22.49,70.43 U39.10 21.08,69.97 C210.1 20.57,73.92 20.32,74.17 19.56,74.17 19.05,74.68 v1(19.05,82.29) ; v1(45.59,86.74) 45.59,91.45 41.63,95.42 38.36,95.42 37.87,94.93 37.36,94.93 37.04,95.25 37.04,95.58 36.95,95.67 U37.7
  BOTTOM w0.152: v1(36.45,98.93) 36.95,98.43 U37.4 U37.7
TYPEC_CC2: length 86.4
  TOP w0.152: J30.B5 27.38,98.3 27.33,98.35 27.33,98.75 27.54,98.96 27.54,99.84 27.05,100.33 v1(25.78,100.33)
  ART03 w0.135: v1(46.1,87.76) 46.1,86.12 42.89,82.91 19.79,82.91 19.65,82.77 19.65,82.58 v1(19.94,82.29)
  BOTTOM w0.135: v1(19.94,82.29) 19.79,82.29 19.36,81.87 19.36,74.8 19.62,74.55 25.27,74.55 26.55,73.27 26.55,71.01 C209.1 25.51,69.97 U39.1 24.39,69.97 23.99,70.37 U39.14 ; U37.6 37.45,95.67 37.36,95.58 37.36,95.38 37.49,95.24 37.74,95.24 38.23,95.73 41.76,95.73 45.91,91.58 45.91,87.95 v1(46.1,87.76)
  BOTTOM w0.152: v1(25.78,100.33) 25.94,100.49 30.52,100.49 31.36,99.64 36.75,99.64 37.45,98.95 U37.5 U37.6
UART0_RX_M0: length 67
  TOP w0.152: J5.60 60.88,22.27 59.94,21.33 59.94,19.3 58.93,18.29 v1(35.43,18.29)
  BOTTOM w0.152: v1(35.43,18.29) 33.78,19.94 33.78,22.6 34.54,23.37 34.54,28.77 32.96,30.35 32.96,32.01 31.5,33.48 31.5,40.64 33.78,42.92 33.78,45.97 35.31,47.5 35.31,48.58 35.61,48.89 U9.9
UART0_TX_M0: length 74.7
  TOP w0.152: J5.64 61.68,20.35 62.03,20 62.03,19.22 61.75,18.94 60.85,18.94 59.69,17.78 34.94,17.78 v1(34.43,18.29)
  BOTTOM w0.152: v1(34.43,18.29) 33.2,19.52 33.2,22.78 33.91,23.49 33.91,28.54 32.33,30.12 32.33,31.93 30.99,33.27 30.99,40.77 33.27,43.05 33.27,46.1 34.8,47.62 34.8,49.91 35.31,50.42 37.72,50.42 37.97,50.17 U9.10
UART4_DIR: length 56.3
  TOP w0.152: J6.72 63.28,73.87 63.58,73.57 v1(64.27,73.57)
  BOTTOM w0.152: U10.2 89.66,47.24 89.92,46.99 90.68,46.99 90.93,47.24 U10.3 90.93,50.28 R65.1 89.78,51.43 66.17,51.43 64.39,53.21 64.39,73.45 v1(64.27,73.57)
UART4_RX_M2: length 40.3
  TOP w0.152: J5.97 68.48,31.52 68.96,32 72.21,32 72.52,32.31 72.52,45.85 75.56,48.89 87.38,48.89 v1(88.39,49.91)
  BOTTOM w0.152: U10.1 v1(88.39,49.91)
UART4_TX_M2: length 43.5
  TOP w0.152: J5.99 68.88,30.86 69.39,31.37 72.72,31.37 73.15,31.8 73.15,45.59 75.95,48.39 90.68,48.39 v1(92.2,49.91)
  BOTTOM w0.152: U10.4 v1(92.2,49.91)
UART7_DIR: length 55
  TOP w0.152: v1(68.94,76.2) 68.44,75.69 67.83,75.69 67.68,75.54 J6.94
  BOTTOM w0.152: U11.2 81.79,47.37 81.92,47.24 82.91,47.24 83.06,47.4 U11.3 83.06,50.28 R73.1 82.39,50.95 65.89,50.95 64.01,52.83 64.01,72.48 63.75,72.74 63.75,73.83 64.06,74.13 66.88,74.13 v1(68.94,76.2)
UART7_RX_M2: length 33.9
  TOP w0.152: J5.93 67.68,32.88 68.2,33.4 71.07,33.4 71.37,33.7 71.37,47.24 74.04,49.91 v1(80.26,49.91)
  BOTTOM w0.152: v1(80.26,49.91) 80.52,49.66 U11.1
UART7_TX_M2: length 36.8
  TOP w0.152: J5.95 68.08,32.33 68.38,32.64 71.5,32.64 71.88,33.02 71.88,45.97 75.31,49.4 83.82,49.4 v1(84.33,49.91)
  BOTTOM w0.152: U11.4 v1(84.33,49.91)
UART9_RX_M2: length 101.6
  TOP w0.152: v1(60.33,73.17) 60.45,73.05 64.48,73.05 64.79,73.35 64.79,73.79 64.08,74.49 J6.76
  ART03 w0.14: v1(29.46,37.59) 30.1,38.23 48.26,38.23 49.17,37.31 60.1,37.31 v1(60.96,36.45)
  BOTTOM w0.152: U9.12 40.51,50.42 39.62,51.31 34.8,51.31 33.78,50.29 33.78,48 32.21,46.43 32.21,43.33 29.97,41.1 29.97,38.1 v1(29.46,37.59) ; v1(60.33,73.17) 60.33,71.19 60.76,70.75 60.76,56.96 59.82,56.02 59.82,53.08 58.42,51.69 58.42,44.32 61.09,41.65 61.09,36.57 v1(60.96,36.45)
UART9_TX_M2: length 92.6
  TOP w0.152: J6.58 60.48,74.33 v1(60.33,74.17)
  ART03 w0.14: v1(30.48,37.59) 48.01,37.59 48.9,36.7 55.63,36.7 55.85,36.93 59.59,36.93 v1(60.07,36.45)
  BOTTOM w0.152: v1(60.07,36.45) 60.65,37.02 60.65,41.46 58.04,44.07 58.04,52.07 59.31,53.34 59.31,56.21 60.33,57.23 60.33,70.45 59.84,70.93 59.84,73.45 60.33,73.93 v1(60.33,74.17) ; v1(30.48,37.59) 30.48,40.89 32.64,43.05 32.64,46.23 34.29,47.88 34.29,50.04 35.05,50.8 38.99,50.8 39.25,50.54 U9.11
USB20_HOST0_DM: length 31.7
  TOP w0.135: v1(86.14,72.62) 86.54,72.62 86.71,72.45 87.18,72.45 87.44,72.72 87.44,73.66 arc(87.41,73.74) 87.33,73.77 arc(87.24,73.81) 87.21,73.89 87.21,74.19 arc(87.24,74.28) 87.33,74.31 arc(87.41,74.35) 87.44,74.43 87.44,74.73 arc(87.41,74.82) 87.33,74.85 arc(87.24,74.89) 87.21,74.97 87.21,75.27 arc(87.24,75.36) 87.33,75.39 arc(87.41,75.42) 87.44,75.51 87.44,76.22 87.18,76.49 81.12,76.49 80.52,77.09 66.8,77.09 66.44,76.72 66.44,75.69 66.48,75.65 J6.88
  BOTTOM w0.135: v1(86.14,72.62) 86.14,72.62 85.96,72.45 85.23,72.45 84.78,72 84.78,71.18 R120.2
USB20_HOST0_DP: length 32.2
  TOP w0.135: v1(86.14,71.96) 86.54,71.96 86.71,72.14 87.3,72.14 87.76,72.59 87.76,76.35 87.3,76.8 81.25,76.8 80.65,77.4 66.67,77.4 66.12,76.85 66.12,75.69 66.08,75.65 J6.86
  BOTTOM w0.135: v1(86.14,71.96) 85.97,72.13 85.36,72.13 85.09,71.87 85.09,71.24 R119.2
USB20_HOST1_DM: length 57.3
  TOP w0.135: J6.82 65.28,74.59 65.49,74.39 71.56,74.39 72.01,73.93 72.01,72.82 v1(72.18,72.64) ; R109.1 97.04,45.85 95.38,45.85 93.91,47.31 93.91,50.36 86.49,57.78 84.25,57.78 v1(84.07,57.96)
  BOTTOM w0.135: v1(72.18,72.64) 72.01,72.47 72.01,58.84 74.64,56.21 77.97,56.21 arc(78.04,56.24) 78.07,56.31 arc(78.1,56.38) 78.17,56.41 78.51,56.41 arc(78.58,56.38) 78.61,56.31 arc(78.64,56.24) 78.71,56.21 79.05,56.21 arc(79.12,56.24) 79.15,56.31 arc(79.18,56.38) 79.25,56.41 79.58,56.41 arc(79.66,56.38) 79.69,56.31 arc(79.72,56.24) 79.79,56.21 81.3,56.21 82.79,57.71 83.82,57.71 v1(84.07,57.96)
USB20_HOST1_DP: length 57.3
  TOP w0.135: v1(71.52,72.64) 71.7,72.82 71.7,73.8 71.43,74.07 65.36,74.07 64.88,74.55 J6.80 ; v1(84.07,57.3) 84.25,57.47 86.36,57.47 93.6,50.23 93.6,47.18 95.25,45.53 97.09,45.53 R108.1
  BOTTOM w0.135: v1(84.07,57.3) 83.98,57.4 82.92,57.4 81.42,55.9 74.51,55.9 71.7,58.71 71.7,72.47 v1(71.52,72.64)
USB20_PWR_EN: length 55.8
  TOP w0.152: v1(96.27,98.04) 95.76,97.53 77.22,97.53 76.33,96.65 76.33,81.91 75.69,81.28 64.01,81.28 63.65,80.92 63.65,79.38 61.68,77.4 J6.64
  BOTTOM w0.152: R124.1 97.02,98.04 v1(96.27,98.04)
USB20_VBUS: length 17.4
  BOTTOM w0.762: J16.10 90.82,90.18 93.09,92.45
  BOTTOM w1.27: 93.09,92.45 97.1,92.45 98.35,91.21 100.13,91.21 101.52,92.6 J17.1 102,93.87 103.76,95.63 103.76,95.63
USB30_PWR_EN: length 43.1
  TOP w0.152: J6.62 61.28,77.56 63.15,79.43 63.15,81.06 63.8,81.71 75.62,81.71 75.95,82.04 75.95,96.9 77.09,98.04 v1(83.06,98.04)
  BOTTOM w0.152: R118.1 83.07,98.05 v1(83.06,98.04)
USB30_SSRXN: length 101.4
  TOP w0.135: J5.21 53.28,28.84 53.24,28.88 53.24,30.28 52.86,30.66 52.86,40.51 59.33,46.99 62.48,46.99 67.45,51.95 73.8,51.95 78.24,56.39 78.24,57.74 77.79,58.19 77.09,58.19 76.67,57.77 76.67,57.22 v1(76.48,57.02)
  BOTTOM w0.135: v1(76.48,57.02) 76.64,57.18 76.64,59.35 73.63,62.36 73.63,74.69 78.28,79.34 82.38,79.34 83.55,80.51 83.55,84.02 83.46,84.12 U17.10 U17.1 83.46,86.11 82,87.57 78.93,87.57 78.04,88.45 78.04,91.56 78.55,92.07 79.38,92.07 arc(79.48,92.11) 79.52,92.21 arc(79.56,92.31) 79.66,92.35 79.92,92.35 arc(80.01,92.31) 80.06,92.21 arc(80.1,92.11) 80.2,92.07 80.45,92.07 arc(80.55,92.11) 80.59,92.21 arc(80.64,92.31) 80.73,92.35 80.99,92.35 arc(81.09,92.31) 81.13,92.21 arc(81.17,92.11) 81.27,92.07 81.53,92.07 82.18,91.42 82.46,91.42 J16.5
USB30_SSRXP: length 101.4
  TOP w0.135: J5.19 52.88,28.84 52.92,28.88 52.92,30.15 52.54,30.53 52.54,40.64 59.2,47.3 62.35,47.3 67.32,52.27 73.67,52.27 77.93,56.52 77.93,57.61 77.66,57.88 77.22,57.88 76.98,57.64 76.98,57.17 v1(77.14,57.02)
  BOTTOM w0.135: v1(77.14,57.02) 76.95,57.21 76.95,59.48 73.94,62.49 73.94,74.56 78.41,79.03 82.51,79.03 83.86,80.38 83.86,84.02 83.96,84.12 U17.9 U17.2 83.95,85.53 83.95,86.06 82.13,87.88 79.06,87.88 78.35,88.58 78.35,91.44 78.68,91.76 81.4,91.76 82.06,91.11 83.36,91.11 84.13,91.88 J16.6
USB30_SSTXN: length 81.7
  TOP w0.135: J5.25 54.08,28.84 54.04,28.88 54.04,29.87 54.67,30.5 54.67,40.39 59.68,45.41 62.68,45.41 68.12,50.84 74.56,50.84 79.6,55.88 79.6,57.19 79.89,57.47 80.76,57.47 v1(80.96,57.28)
  BOTTOM w0.135: C97.2 85.19,81.32 85.19,80.04 83.06,77.91 78.64,77.91 75.1,74.37 75.1,63.05 78.23,59.92 78.23,58.2 79.09,57.34 80.89,57.34 v1(80.96,57.28)
USB30_SSTXP: length 81.7
  TOP w0.135: v1(80.96,57.94) 80.81,57.78 79.76,57.78 79.29,57.32 79.29,56.01 74.43,51.15 67.99,51.15 62.55,45.72 59.55,45.72 54.36,40.52 54.36,30.63 53.72,30 53.72,28.88 53.68,28.84 J5.23
  BOTTOM w0.135: v1(80.96,57.94) 80.95,57.94 80.67,57.66 79.21,57.66 78.54,58.33 78.54,60.05 75.41,63.18 75.41,74.24 78.77,77.6 83.19,77.6 85.5,79.91 85.5,81.32 C98.2
USB30_VBUS: length 2.5
  BOTTOM w1.27: 90.42,95.88 90.42,95.88 J16.1
USER_LED: length 57.5
  TOP w0.152: v1(63.08,26.77) 62.48,27.37 J5.67
  ART03 w0.14: v1(13.72,20.06) 14.08,20.43 32.54,20.43 33.5,21.39 33.5,24.41 33.78,24.69 62.8,24.69 63.08,24.97 v1(63.08,26.77)
  BOTTOM w0.152: v1(13.72,20.06) R39.1
WLAN_PWR_EN: length 58.8
  TOP w0.152: v1(65.02,72.57) 59.58,72.57 59.28,72.87 J6.52
  BOTTOM w0.152: v1(65.02,72.57) 64.77,72.31 64.77,53.34 66.29,51.81 94.11,51.81 94.37,51.55 R111.1
N03801: length 3.8
  TOP w0.203: U3.4 v1(2.67,53.91)
  BOTTOM w0.254: C10.2 R6.2 R7.1 2.72,53.97 v1(2.67,53.91)
N15118698: length 9.5
  BOTTOM w0.152: R3.2 C4.1 23.77,40.5 U1.4 23.94,42.1 24.89,43.05 24.89,44.42 23.77,45.55 U2.4
N15119063: length 1.9
  BOTTOM w0.152: U1.3 26.27,41 26.04,40.77 R4.1
N15123057: length 1.8
  BOTTOM w0.152: R5.1 26.03,45.72 26.27,45.95 U2.3
N15599533: length 3.3
  BOTTOM w0.132: U14.25 111.83,64.43 R84.2
N15599537: length 3.9
  BOTTOM w0.132: U14.24 112.23,64.55 113.15,63.63 113.78,63.63 R85.2
N15599541: length 4.9
  BOTTOM w0.132: U14.23 112.63,64.55 113.12,64.06 114.88,64.06 115.44,63.5 R87.2
N15599545: length 5.6
  BOTTOM w0.132: U14.22 113.03,64.55 113.2,64.39 115.7,64.39 116.59,63.5 R88.2
N15599549: length 2.8
  BOTTOM w0.132: U14.27 111.03,65.15 111.09,65.09 111.09,63.82 110.87,63.6 R89.2
N15599553: length 3
  BOTTOM w0.132: U14.26 111.43,63.69 R90.2
N15600826: length 8.6
  BOTTOM w0.152: U14.31 108.82,66.52 108.62,66.33 108.62,65.34 107.07,63.79 107.07,62.25 R95.2 105.96,61.14 105.1,61.14 R96.2
N15601838: length 4.9
  BOTTOM w0.152: U14.37 106.64,68.92 C74.1 106.21,68.5 105.49,68.5 105.27,68.72 Y2.1
N15601846: length 6.3
  BOTTOM w0.152: Y2.3 103.77,67.32 104.65,68.2 106.16,68.2 C75.1 107.27,68.52 U14.36
N15602572: length 5.2
  BOTTOM w0.152: R104.1 106.54,63.69 108.32,65.47 108.32,66.66 108.58,66.92 U14.32
N15603170: length 3.1
  TOP w0.254: J15.1 122.72,82.76 C76.1
N15603215: length 28.3
  BOTTOM w0.508: J15.15 J15.16 107.92,89.72 107.92,82.78 C77.1 104.52,81.91 R101.1
N15604636: length 3.6
  BOTTOM w0.152: R100.1 117.53,99 J15.12
N15605512: length 4.6
  BOTTOM w0.152: U14.39 108.58,69.72 108.33,69.98 108.33,72.91 R86.1
N15611443: length 5.3
  BOTTOM w0.152: U20.4 85.92,101.15 85.72,101.34 83.95,101.34 83.7,101.1 C100.1 83.69,100.07 R118.2
N15611553: length 3.3
  BOTTOM w0.152: R121.1 84.71,96.93 84.86,96.77 85.72,96.77 85.92,96.97 U20.3
N15654067: length 3.3
  BOTTOM w0.152: R125.1 98.04,97.03 98.3,96.77 99.06,96.77 99.25,96.97 U21.3
N15659726: length 6.4
  TOP w0.203: U3.5 v1(2.67,52.96)
  BOTTOM w0.254: R8.2 R9.1 C18.2 2.42,55 2.13,54.71 2.13,53.49 v1(2.67,52.96)
N15752445: length 31.8
  TOP w0.508: J18.G1 J18.G3 ; J18.G2 J18.G4
  BOTTOM w0.508: L5.1 78.17,100.1 J18.G4 73,101.34 61,101.34 J18.G3
N16793147: length 6
  TOP w0.132: R53.2 114.43,26.68 114.43,25.41 D11.2 113.79,23.75 113.3,23.26 J10.1
N16793149: length 5.9
  TOP w0.132: J10.7 106.7,23.22 106.43,23.49 D15.2 105.79,25.41 105.79,26.68 R58.2
N16793151: length 6.3
  TOP w0.132: J10.5 108.9,22.93 107.7,24.13 D14.2 107.06,25.41 107.06,26.68 R57.2
N16793153: length 5.9
  TOP w0.132: R55.2 111.89,26.68 111.89,25.41 D13.2 111.25,23.49 111.1,23.34 J10.3
N16793155: length 6
  TOP w0.132: J10.2 112.2,23.04 112.52,23.37 D12.2 113.16,25.41 113.16,26.68 R54.2
N16793157: length 6
  TOP w0.132: J10.8 105.6,23.3 105.16,23.75 D16.2 104.52,25.41 104.52,26.68 R59.2
N16793300: length 6.1
  TOP w0.152: R60.2 103.25,26.68 103.25,25.41 D17.2 103.89,23.87 104.5,23.26 J10.9
N16811933: length 3.7
  TOP w0.152: v1(119.89,80.52) 119.6,80.23 J25.1
  BOTTOM w0.152: R177.2 R178.2 119.88,80.51 v1(119.89,80.52)
N16823854: length 2.8
  TOP w0.152: v1(117.73,80.52) 117.2,79.99 J25.7
  BOTTOM w0.152: v1(117.73,80.52) 117.72,80.51 R179.2
N16928945: length 5.9
  TOP w0.152: J25.20 108.8,69.05 107.31,67.56 R180.1
N16929135: length 4.6
  TOP w0.203: R181.1 107.44,68.58 108,69.14 J25.22
N16980859: length 14.1
  BOTTOM w0.152: R170.2 C155.1 114.31,33.03 115.22,32.11 115.22,31.34 115.69,30.87 U32.6 116.12,30.39 114.94,29.21 114.94,24.76 113.29,23.12 J31.2
N16980861: length 16
  BOTTOM w0.152: J31.3 115.83,28.71 117.47,30.35 117.47,31.49 116.98,31.99 116.67,31.99 116.55,31.87 U32.4 116.12,32.43 C154.1 116.08,33.66 116.08,34.93 R171.2
N16980863: length 17.2
  BOTTOM w0.152: J31.7 114.56,23.12 115.44,24 115.44,28.95 116.84,30.35 116.84,31.24 116.71,31.37 U32.5 115.69,31.37 115.57,31.49 115.57,32.38 115.44,32.51 C153.1 114.81,33.66 114.81,34.93 R169.2 R173.2
N17454508: length 2.7
  BOTTOM w0.254: U9.1 45.59,42.42 C56.2
N17454513: length 2.3
  BOTTOM w0.254: U9.3 43.05,41.41 C56.1
N17455367: length 2.2
  BOTTOM w0.254: C57.2 41.65,43.17 U9.4
N17455372: length 2.2
  BOTTOM w0.254: U9.5 40.51,41.29 C57.1
N17455499: length 2.3
  BOTTOM w0.254: U9.6 39.25,41.51 C55.1
N17455508: length 4.6
  BOTTOM w0.254: C53.1 46.11,45.21 44.58,45.21 44.33,44.96 U9.2
N17592125: length 1.4
  TOP w0.381: C145.1 84.32,82.05 U30.6
N17592172: length 4.7
  TOP w0.254: C146.2 R172.2 R174.1 82.3,80.13 82.04,80.38 82.04,82.04 U30.4
N17592220: length 3.5
  TOP w0.152: U30.5 83.19,81.51 v1(82.58,80.9)
  BOTTOM w0.152: R175.2 R176.1 82.29,81.19 v1(82.58,80.9)
N17633217: length 5.9
  BOTTOM w0.152: Y3.1 96.51,69.33 95.68,68.5 94.06,68.5 C103.1 93.46,68.57 U19.3
N17633237: length 4.8
  BOTTOM w0.152: Y3.3 95.01,68.06 94.87,68.2 94.12,68.2 C102.2 93.46,68.08 U19.4
N17633305: length 3.8
  BOTTOM w0.152: U19.18 87.18,71 88.27,72.09 R123.2
N17633317: length 7
  BOTTOM w0.152: U19.16 86.49,68.57 86.23,68.83 86.23,70.79 87.55,72.11 87.55,73.19 R122.2
N17695706: length 11
  TOP w0.152: R156.2 C128.1 130.46,89.64 U25.4 129.79,89.71 129.79,90.55 130.05,90.8 131.32,90.8 131.7,91.18 131.7,94.29 131.39,94.59 U26.4
N17695791: length 1.8
  TOP w0.203: U26.3 130.63,92.09 130.94,92.4 R159.1
N17695827: length 1.7
  TOP w0.203: R158.1 129.73,85.92 U25.3
N17697466: length 3.6
  BOTTOM w0.152: J15.13 116.4,99 R99.1
N17697880: length 2.7
  TOP w0.152: U28.3 130.24,58.94 v1(130.18,58.88)
  BOTTOM w0.152: R166.1 129.92,59.14 v1(130.18,58.88)
N17697953: length 3.8
  TOP w0.152: U28.4 v1(129.54,62.46)
  BOTTOM w0.152: R165.2 C139.1 128.41,61.33 v1(129.54,62.46)
N17702194: length 4
  TOP w0.305: R68.2 88.81,14.51 89.09,14.23 J12.3
N17702199: length 4
  TOP w0.305: J12.4 85.28,14.23 85.72,14.67 R69.2
N17702222: length 4
  TOP w0.305: J12.2 92.9,14.23 93.34,14.67 R67.2
N17702231: length 4
  TOP w0.305: J12.1 96.71,14.23 96.43,14.51 R66.2
N17728858: length 5.7
  BOTTOM w0.305: R62.1 93.22,41.15 93.6,41.53 D19.1
N17729021: length 5.7
  BOTTOM w0.305: D23.1 85.72,41.45 85.42,41.15 R70.1
N17731608: length 18.7
  BOTTOM w0.254: R51.2 36.45,17.27 35.69,16.51 35.69,11.76 36.53,10.92 42.97,10.92 J9.4
N17731627: length 19.7
  BOTTOM w0.254: R49.2 44.07,17.47 47.12,14.43 47.12,11.43 47.62,10.92 54.4,10.92 J9.1
N17750545: length 5.3
  BOTTOM w0.152: R12.2 10.91,63.97 Q1.1 11.37,66.13 11.7,66.46 Q2.3
N17750554: length 32.8
  BOTTOM w0.508: Q1.3 10.41,68.48 9.68,69.21 9.68,70.93 9.14,71.47 9.14,75.1 11.2,77.15 11.2,81.69 12.88,83.36 D2.1 J2.1
N17750632: length 2.3
  BOTTOM w0.152: R13.2 R16.1 13.96,63.85 Q2.1
N17770939: length 4
  BOTTOM w0.135: U19.15 86.49,68.08 86.39,67.98 85.39,67.98 85.12,68.25 85.12,69.05 85.47,69.4 R119.1
N17770942: length 4.5
  BOTTOM w0.135: U19.14 86.49,67.57 86.4,67.66 85.26,67.66 84.81,68.12 84.81,69.05 84.45,69.4 R120.1
N17946485: length 7
  TOP w0.381: SW3.3 v1(3.49,28.85) SW3.4
  BOTTOM w0.254: R28.1 C43.1 Z5.2 3.52,28.82 v1(3.49,28.85)
N18056005: length 9.1
  BOTTOM w0.152: R111.2 95.37,46.11 95.66,45.82 96.27,45.82 Q6.1 96.77,44.42 C94.2 R110.2
N18056634: length 9.9
  TOP w0.508: C91.1 108.09,37.71 C92.1 108.08,38.3 arc(108.25,39.15) 108.72,39.86 110.89,42.03 arc(111.92,42.72) 113.14,42.96 U15.2
N18056637: length 2.2
  TOP w0.508: CN1.1 C93.1 108.09,34.68 C91.2
N18057251: length 4
  TOP w0.135: J25.36 102.4,69.74 102.31,69.65 102.31,68.4 101.85,67.94 101.59,67.94 R182.1
N18057253: length 3.5
  TOP w0.135: R183.1 101.5,68.29 101.76,68.29 102,68.53 102,69.35 101.6,69.74 J25.38
N18057325: length 4.7
  TOP w0.135: R109.2 98.76,45.88 101.26,45.88 101.52,46.15 U15.7
N18057335: length 4.7
  TOP w0.135: U15.6 101.52,45.29 101.24,45.57 98.78,45.57 R108.2
N18111918: length 8.9
  TOP w0.152: U27.4 117.16,64.58 116.59,64.01 116.59,60.32 117.16,59.75 U24.4 117.16,58.23 C125.1 R155.2
N18111989: length 1.5
  TOP w0.152: U27.3 117.16,68.13 R160.1
N18112037: length 1.5
  TOP w0.152: R157.1 117.16,62.29 U24.3
N18115454: length 4
  TOP w0.152: R168.1 131.44,36.96 131.19,36.7 130.43,36.7 130.24,36.89 U29.3
N18115527: length 3.8
  TOP w0.152: v1(129.41,40.51) 130.09,40.51 U29.4
  BOTTOM w0.152: R167.2 C142.1 128.39,39.49 v1(129.41,40.51)
N18211307: length 4.4
  TOP w0.254: v1(6.99,70.11) 6.98,70.11 U4.9
  BOTTOM w0.279: R21.1 R19.1 4.97,69.83 C30.1 6.71,69.83 v1(6.99,70.11)
N18211553: length 1.8
  TOP w0.279: U4.7 4.7,69.34 4.06,68.71
N18211596: length 3.4
  TOP w0.203: v1(2.79,72.12) 2.79,72.01 3.19,71.61 U4.3
  BOTTOM w0.279: v1(2.79,72.12) 2.79,70.48 3.17,70.1 R19.2
N18211602: length 3.5
  TOP w0.203: v1(2.68,69.48) 2.54,69.62 2.54,69.96 2.69,70.11 U4.6
  BOTTOM w0.279: v1(2.68,69.48) 3.07,69.09 R21.2 R22.2
N18211651: length 5.4
  TOP w0.203: v1(8,71.11) 7.2,71.11 7.2,71.11 6.77,71.11 6.77,71.11 U4.11
  BOTTOM w0.381: R20.1 R18.2 8.6,69.68 8.6,70.52 v1(8,71.11)
N18211688: length 3.7
  TOP w0.279: U4.8 5.2,69.48 5.34,69.33 5.83,69.33
  TOP w0.381: 5.83,69.33 R14.1
N18213641: length 3.3
  TOP w0.203: U4.12 v1(6.99,71.61)
  BOTTOM w0.279: v1(6.99,71.61) 7.23,71.61 7.99,72.38 R17.2 R15.2
N18241743: length 22.3
  TOP w0.508: J30.2 31.64,101.98 24.36,101.98 J30.3
  ART03 w0.508: J30.1 J30.2
  BOTTOM w0.508: J30.4 J30.3 ; J30.2 31.64,101.98 29.5,101.98 L7.1
N18284542: length 5
  BOTTOM w0.152: C123.1 70.6,89.75 71.06,90.21 Q8.1 70.21,91.18 68.57,91.18 R130.2
N18285221: length 7.1
  BOTTOM w0.152: Q10.1 71.06,97.09 70.8,97.34 68.77,97.34 67.91,98.21 Q11.3 66.93,99.07 R135.2
N18285616: length 15.6
  TOP w0.152: R139.1 75.56,89.42 75.56,91.39 75.13,91.82 72.97,91.82 72.64,92.15 v1(72.64,94.61)
  BOTTOM w0.152: v1(72.64,94.61) 72.26,94.23 68.19,94.23 R142.1 67.43,95.03 67.88,95.49 Q11.1
N18287294: length 2.8
  TOP w0.254: R134.2 R136.2 68.96,85.22 Q15.3
N18287307: length 2.6
  TOP w0.254: Q14.3 65.91,84.62 R138.2 R137.2
N18287331: length 2.5
  TOP w0.254: R141.2 R140.2 Q13.3
N18287355: length 3.7
  TOP w0.254: Q12.3 71.21,84.49 70.61,85.09 R144.2 R143.2
N18312149: length 2.6
  BOTTOM w0.152: R198.2 49.67,72.51 U33.27
N18312152: length 2.6
  BOTTOM w0.152: R197.2 50.12,72.48 U33.28
N18312155: length 2.5
  BOTTOM w0.152: R195.2 50.12,63.92 U33.8
N18312158: length 3.3
  BOTTOM w0.152: U33.7 50.77,64.28 R194.2
N18312161: length 4.4
  BOTTOM w0.152: R193.2 51.56,64.51 51.56,67.12 51.26,67.43 U33.6
N18312164: length 5.6
  BOTTOM w0.152: R191.2 52.07,65.01 52.07,67.56 51.76,67.87 U33.5
N18312167: length 6.9
  BOTTOM w0.152: R190.2 53.39,65.78 53.09,66.09 53.09,69.21 52.62,69.67 U33.1
N18314752: length 4.6
  BOTTOM w0.203: U33.17 46.12,67.87 46.06,67.82 45.59,67.82 45.47,67.7
  BOTTOM w0.381: 45.47,67.7 C166.1 C167.1 R186.2
N18314935: length 4.8
  BOTTOM w0.203: U33.16 45.96,67.43 45.47,66.93
  BOTTOM w0.381: R187.2 C169.1 C168.1 45.2,66.67 45.47,66.93
N18315822: length 2.8
  BOTTOM w0.203: C176.1 47.37,72.24 48.32,71.29 U33.24
N18315825: length 3.1
  BOTTOM w0.203: U33.23 47.87,71.21 46.35,72.72 C177.1
N18315828: length 3.6
  BOTTOM w0.203: C178.1 45.34,72.21 45.54,72.01 46,72.01 47.42,70.59 U33.22
N18315831: length 4.4
  BOTTOM w0.203: C179.1 44.32,72.72 45.39,71.65 45.85,71.65 46.77,70.74 U33.21
